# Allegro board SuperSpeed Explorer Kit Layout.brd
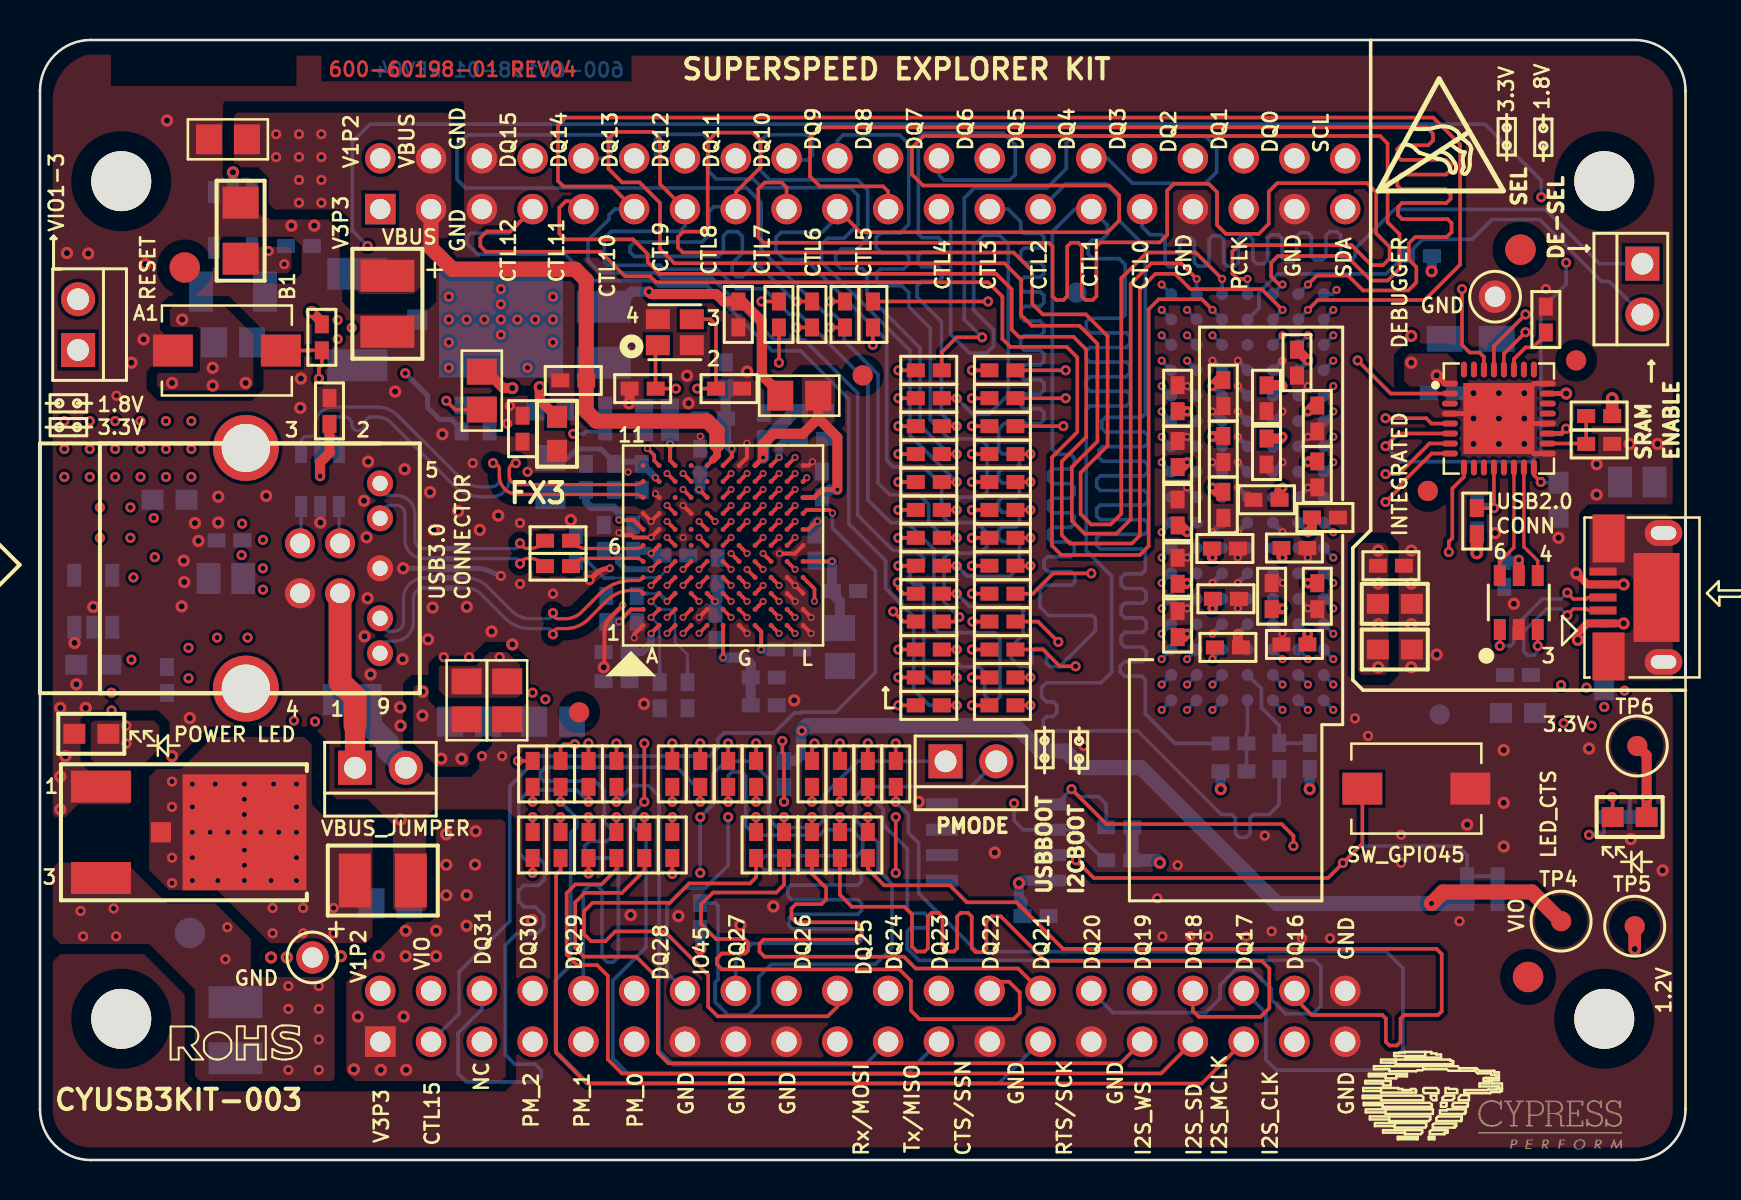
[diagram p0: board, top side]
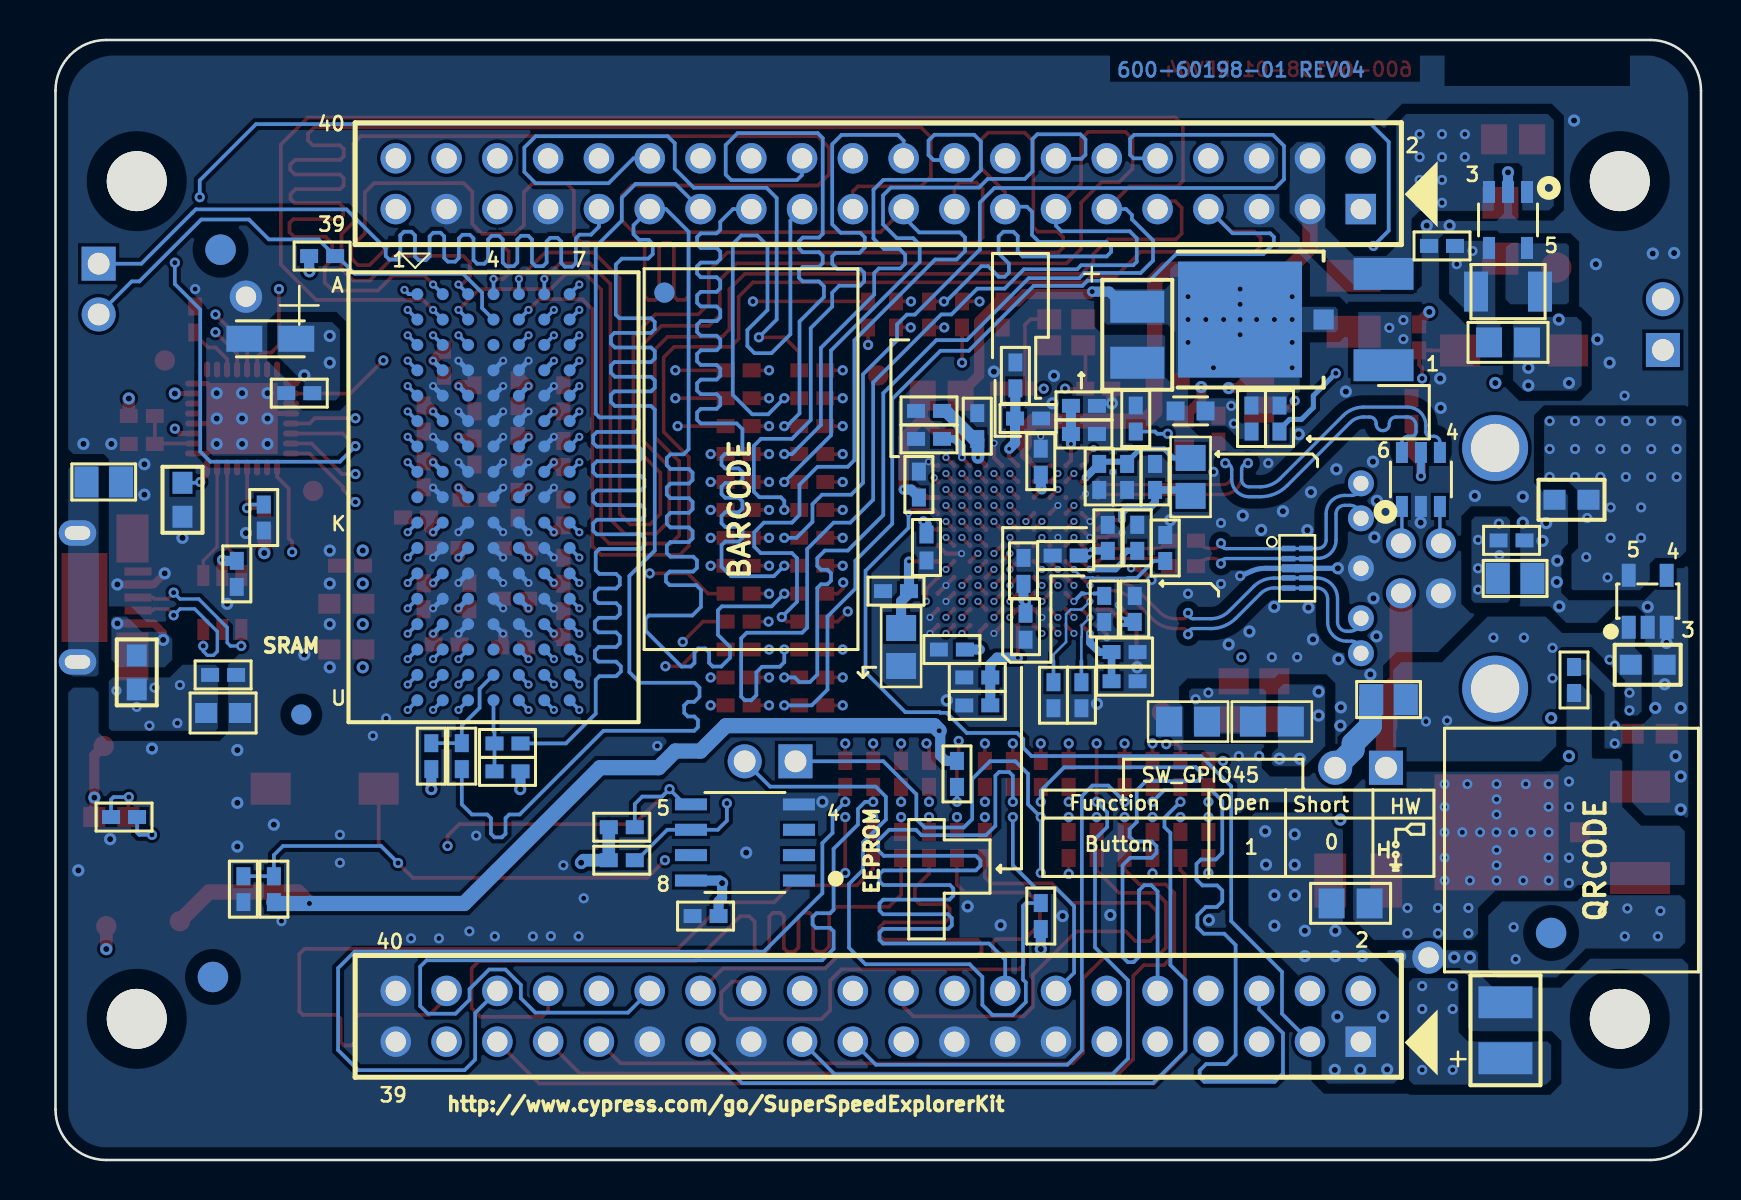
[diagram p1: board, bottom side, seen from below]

Outline 82.3 x 56.04 mm; copper layers: TOP, L02_GND1, L03_SIG1, L04_PWR1, L05_PWR2, L06_SIG2, L07_GND2, BOTTOM. Coordinates in mm from the lower left corner of the outline.
Outline path: 0,53.5 0,2.54 arc(0.74,0.74) 2.54,0 79.76,0 arc(81.55,0.74) 82.3,2.54 82.3,53.5 arc(81.55,55.29) 79.76,56.04 2.54,56.04 arc(0.74,55.29) 0,53.5

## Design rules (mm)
net group CRYSTAL: nets XTALIN XTALOUT
net group CTL3: nets CTL3 N16680016
net group CTL4_SW: nets CTL4_SW N16680012
net group DIFFPAIR0: nets SS_RX_M SS_RX_P
net group DIFFPAIR2: nets SS_DM SS_DP
net group DIFFPAIR3: nets SS_TX_M SS_TX_P
net group DIFFPAIR4.1: nets D+ D-
net group DIFFPAIR5: nets N16689306 N16689332
net group DIFFPAIR6: nets N16695553 N16695561
net group GPIO57_I2S-MCLK_VIO3_SW: nets GPIO57_I2S-MCLK_VIO3_SW N16684510
net group I2S_CLK: nets I2S_CLK N16684396
net group I2S_SD: nets I2S_SD N16684392
net group I2S_WS: nets I2S_WS N16684460
net group PCLK: nets N16679940 PCLK
net group SPI-MISO_UART-TX: nets N16684546 SPI-MISO_UART-TX
net group SPI-MOSI_UART-RX: nets N16684574 SPI-MOSI_UART-RX
net group SPI-SCK_UART-RTS: nets N16684554 SPI-SCK_UART-RTS
net group CTL0: nets N16679936
net group CTL1: nets CTL1 N16679932 N16736019
net group CTL2: nets CTL2 N16679976 N16736247
net group CTL5: nets N16680040
net group CTL6: nets N16680036
net group CTL7: nets N16678748
net group CTL8: nets N16678744
net group CTL9: nets N16678772
net group CTL10: nets N16678768
net group CTL11: nets N16678828
net group CTL12: nets N16678842
net group DQ0: nets N16678980
net group DQ1: nets N16679050
net group DQ2: nets N16679094
net group DQ3: nets N16679146
net group DQ4: nets N16679214
net group DQ5: nets N16679210
net group DQ6: nets N16679206
net group DQ7: nets N16679250
net group DQ8: nets N16679750
net group DQ9: nets N16679746
net group DQ10: nets N16679742
net group DQ11: nets N16679786
net group DQ12: nets N16679856
net group DQ13: nets N16679852
net group DQ14: nets N16679880
net group DQ15: nets N16679876
net group DQ16: nets N16683812
net group DQ17: nets N16683802
net group DQ18: nets N16683838
net group DQ19: nets N16683870
net group DQ20: nets N16683912
net group DQ21: nets N16683942
net group DQ22: nets N16683932
net group DQ23: nets N16683968
net group DQ24: nets N16684000
net group DQ25: nets N16684042
net group DQ26: nets N16684068
net group DQ27: nets N16684104
net group DQ28: nets N16684224
net group DQ29: nets N16684254
net group DQ30: nets N16684244
net group DQ31: nets N16684280

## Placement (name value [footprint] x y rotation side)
C1  10uF_10V  [CC0805]  9.4 51.07 180 top
C2  22uF_6.3V  [CC1206]  10.03 46.5 90 top
C3  0.1uF_25V  [C0402]  14.48 37.48 90 top
C4  22 uFd 16v  [C-PCC3528]  17.14 13.98 0 top
C5  10 uFd 25v  [C-PCC3528]  17.37 42.84 270 top
C6  22UF_16V  [C0805]  23.37 23 270 top
C7  2.2uF_25V  [C0603]  25.86 36.34 270 top
C8  0.1uF_25V  [C0402]  25.91 30.98 180 top
C9  0.1uF_25V  [C0402]  25.91 29.71 180 top
C10  0.1uF_25V  [C0402]  26.67 39 180 top
C11  13pF_50V  [C0402]  30.14 38.59 180 top
C12  13pF_50V  [C0402]  34.46 38.59 180 top
C13  0.1uF_25V  [C0402]  56.9 38.11 90 top
C14  0.1uF_25V  [C0402]  56.9 35.32 90 top
C15  0.1uF_25V  [C0402]  56.9 32.4 90 top
C16  0.1uF_25V  [C0402]  56.9 29.48 90 top
C17  0.1uF_25V  [C0402]  56.9 26.81 90 top
C18  0.1uF_25V  [C0402]  59.18 38.37 270 top
C19  0.1uF_25V  [C0402]  59.18 35.57 270 top
C20  0.1uF_25V  [C0402]  59.18 32.78 270 top
C21  0.1uF_25V  [C0402]  59.26 30.6 0 top
C22  0.1uF_25V  [C0402]  59.31 28.08 0 top
C23  0.1uF_25V  [C0402]  61.34 38.11 270 top
C24  0.1uF_25V  [C0402]  61.34 35.45 270 top
C25  0.1uF_25V  [C0402]  61.34 33.03 180 top
C26  0.1uF_25V  [C0402]  61.59 28.21 90 top
C27  0.1uF_25V  [C0402]  62.74 30.62 0 top
C28  0.1uF_25V  [C0402]  62.74 25.79 180 top
C29  0.1uF_25V  [C0402]  62.86 39.89 270 top
C30  0.1uF_25V  [C0402]  63.88 37.1 270 top
C31  0.1uF_25V  [C0402]  63.88 34.3 270 top
C32  0.1uF_25V  [C0402]  63.88 28.21 270 top
C33  0.1uF_25V  [C0402]  64.26 32.14 0 top
C34  0.1uF_25V  [C0402]  67.56 29.73 0 top
C35  2.2uF_25V  [C0603]  67.76 27.83 0 top
C36  2.2uF_25V  [C0603]  67.76 25.54 0 top
C37  0.01uF_25V  [C0402]  77.98 35.83 0 top
C38  1UF_16V  [CC0603]  75.95 33.03 90 bottom
C39  0.1uF_25V  [C0402]  73.23 29.33 270 bottom
C40  0.1uF_25V  [C0402]  72.9 13.55 270 bottom
C41  4.7uF / 25V  [CAPMP3216X180N]  71.55 41.09 0 bottom
C42  0.1uF_25V  [C0402]  70.1 38.37 0 bottom
C43  0.1uF_25V  [C0402]  49.78 12.21 0 bottom
C44  0.1uF_25V  [C0402]  40.26 28.46 0 bottom
C45  22UF_16V  [C0805]  40.01 25.67 270 bottom
C46  0.01uF_25V  [C0402]  39.12 33.8 90 bottom
C47  0.1uF_25V  [C0402]  38.73 30.65 270 bottom
C48  0.1uF_25V  [C0402]  38.61 37.48 0 bottom
C49  0.01uF_25V  [C0402]  38.61 36.08 0 bottom
C50  0.1uF_25V  [C0402]  37.47 25.54 0 bottom
C51  0.1uF_25V  [C0402]  36.2 36.72 90 bottom
C52  0.01uF_25V  [C0402]  36.2 24.14 0 bottom
C53  0.1uF_25V  [C0402]  36.2 22.75 0 bottom
C54  0.1uF_25V  [C0402]  34.29 39.26 90 bottom
C55  0.1uF_25V  [C0402]  33.88 29.48 90 bottom
C56  0.01uF_25V  [C0402]  33.78 26.68 270 bottom
C57  0.1uF_25V  [C0402]  33.66 37.1 180 bottom
C58  0.01uF_25V  [C0402]  33.02 34.94 90 bottom
C59  0.01uF_25V  [C0402]  31.78 30.24 0 bottom
C60  0.01uF_25V  [C0402]  30.86 37.73 180 bottom
C61  0.1uF_25V  [C0402]  30.86 36.32 180 bottom
C62  0.1uF_25V  [C0402]  30.1 34.18 270 bottom
C63  0.01uF_25V  [C0402]  29.84 27.57 270 bottom
C64  0.1uF_25V  [C0402]  29.67 31.13 90 bottom
C65  0.01uF_25V  [C0402]  28.83 25.41 180 bottom
C66  0.1uF_25V  [C0402]  28.83 23.95 180 bottom
C67  0.01uF_25V  [C0402]  28.7 34.18 270 bottom
C68  0.1uF_25V  [C0402]  28.32 27.57 90 bottom
C69  22 uFd 16v  [C-PCC3528]  28.19 41.29 270 bottom
C70  0.1uF_25V  [C0402]  28.19 31.13 90 bottom
C71  0.1uF_25V  [C0402]  27.3 34.18 90 bottom
C72  0.1uF_25V  [C0402]  26.8 30.62 90 bottom
C73  22UF_16V  [C0805]  25.65 21.93 0 bottom
C74  1.0 uF  [CAPC1608X90N_B]  25.53 37.48 0 bottom
C75  10 uFd 25v  [C-PCC3528]  9.78 6.49 90 bottom
C76  0.1uF_25V  [C0402]  9.47 31 180 bottom
C77  1UF_16V  [CC0603]  6.48 33.03 0 bottom
C78  0.1uF_25V  [C0402]  73.91 24.27 180 bottom
C79  1UF_16V  [CC0603]  73.91 22.37 0 bottom
C80  1UF_16V  [CC0603]  2.67 24.78 180 bottom
FB1  MPZ2012S601A  [FB0805]  21.34 23 270 top
FB2  MPZ2012S601A  [FB0805]  22.1 38.49 270 top
FB3  120E  [EMIFIL_BLM18P_0603]  78.23 24.4 270 bottom
FB4  MPZ2012S601A  [FB0805]  25.53 34.18 90 bottom
FB5  MPZ2012S601A  [FB0805]  21.46 21.93 180 bottom
J1  -  [UEB1112C-2AK1-4H]  3 29.6 270 top
J2  961102-6404-AR  [TE_825433-2]  1.91 40.53 90 top
J3  961102-6404-AR  [TE_825433-2]  15.76 19.63 0 top
J4  961102-6404-AR  [TE_825433-2]  45.29 19.95 0 top
J5  961102-6404-AR  [TE_825433-2]  80.14 44.84 270 top
J6  613 040 211 21  [SSW-120-03-G-D]  17.02 50.12 0 bottom
J7  613 040 211 21  [SSW-120-03-G-D]  17.02 8.46 0 bottom
J8  -  [DX4R005J91R1500]  82.3 28.15 90 top
L1  -  [BLM21PG221SN1D]  79.88 33.92 180 bottom
L2  -  [BLM21PG221SN1D]  15.63 23.04 180 bottom
L3  2.2uH  [NLCV32T-2R2M-PFR]  9.65 43.45 0 bottom
L4  -  [BLM21PG221SN1D]  9.3 29.1 180 bottom
LED1  LED_GREEN  [LED_0603]  2.57 21.32 180 top
LED2  LED_BLUE  [LED_0603]  79.5 17.16 180 top
NOREF  -  [unnamed]  74.42 9.16 0 top
NOREF#2  -  [#2]  80.29 0.06 0 top
NOREF#3  -  [#2]  -86.87 22.94 0 top
NOREF#4  -  [#2]  0 2.54 0 top
NOREF#5  -  [unnamed]  7.24 44.66 0 top
NOREF#6  -  [unnamed]  78.23 48.97 0 top
NOREF#7  -  [#2]  2.57 0 90 top
NOREF#8  -  [#2]  14.1 77.17 0 top
NOREF#9  -  [unnamed]  78.23 7.06 0 top
NOREF#10  -  [#2]  14.1 40.34 0 top
NOREF#11  -  [unnamed]  74.04 45.54 0 top
NOREF#12  -  [unnamed]  26.96 22.4 90 top
NOREF#13  -  [unnamed]  4.06 7.06 0 top
NOREF#14  -  [#2]  14.1 77.17 0 top
NOREF#15  -  [unnamed]  69.41 33.48 90 top
NOREF#16  -  [unnamed]  41.15 39.26 90 top
NOREF#17  -  [unnamed]  76.82 40 90 top
NOREF#18  -  [#2]  2.54 0 90 top
NOREF#19  -  [unnamed]  4.06 48.97 0 top
NOREF#20  -  [#2]  0 50.5 0 top
NOREF#21  -  [unnamed]  74.42 9.16 180 bottom
NOREF#22  -  [unnamed]  51.84 43.4 0 bottom
NOREF#23  -  [unnamed]  7.5 11.36 180 bottom
NOREF#24  -  [unnamed]  74.04 45.54 180 bottom
NOREF#25  -  [unnamed]  70 22.29 270 bottom
R1  100K  [R0402]  14.1 41.16 90 top
R2  1.96K  [R0402]  24.13 36.59 90 top
R3  22 Ohm  [R0402]  24.64 19.32 270 top
R4  22 Ohm  [R0402]  24.64 15.76 270 top
R5  22 Ohm  [R0402]  26.04 19.32 270 top
R6  22 Ohm  [R0402]  26.04 15.76 270 top
R7  22 Ohm  [R0402]  27.43 19.32 270 top
R8  22 Ohm  [R0402]  27.43 15.76 270 top
R9  22 Ohm  [R0402]  28.83 19.32 270 top
R10  22 Ohm  [R0402]  28.83 15.76 270 top
R11  22 Ohm  [R0402]  30.23 15.76 270 top
R12  22 Ohm  [R0402]  31.62 19.32 270 top
R13  22 Ohm  [R0402]  31.62 15.76 270 top
R14  22 Ohm  [R0402]  33.02 19.32 270 top
R15  22 Ohm  [R0402]  34.42 19.32 270 top
R16  180 Ohm  [R0402]  34.92 42.3 90 top
R17  22 Ohm  [R0402]  35.81 19.32 270 top
R18  22 Ohm  [R0402]  35.81 15.76 270 top
R19  22 Ohm  [R0402]  36.96 42.3 90 top
R20  22 Ohm  [R0402]  37.21 15.76 270 top
R21  0 Ohm  [CC0805]  37.97 38.24 0 top
R22  22 Ohm  [R0402]  38.61 42.3 90 top
R23  22 Ohm  [R0402]  38.61 19.32 270 top
R24  22 Ohm  [R0402]  38.61 15.76 270 top
R25  22 Ohm  [R0402]  40.01 19.32 270 top
R26  22 Ohm  [R0402]  40.01 15.76 270 top
R27  22 Ohm  [R0402]  40.26 42.3 90 top
R28  22 Ohm  [R0402]  41.4 19.32 270 top
R29  22 Ohm  [R0402]  41.4 15.76 270 top
R30  22 Ohm  [R0402]  41.66 42.3 90 top
R31  22 Ohm  [R0402]  42.8 19.32 270 top
R32  22 Ohm  [R0402]  44.45 39.51 0 top
R33  22 Ohm  [R0402]  44.45 38.11 0 top
R34  22 Ohm  [R0402]  44.45 36.72 0 top
R35  22 Ohm  [R0402]  44.45 35.32 0 top
R36  22 Ohm  [R0402]  44.45 33.92 0 top
R37  22 Ohm  [R0402]  44.45 32.53 0 top
R38  22 Ohm  [R0402]  44.45 31.13 0 top
R39  22 Ohm  [R0402]  44.45 29.73 0 top
R40  22 Ohm  [R0402]  44.45 28.33 0 top
R41  22 Ohm  [R0402]  44.45 26.94 0 top
R42  22 Ohm  [R0402]  44.45 25.54 0 top
R43  22 Ohm  [R0402]  44.45 24.14 0 top
R44  22 Ohm  [R0402]  44.45 22.75 0 top
R45  22 Ohm  [R0402]  48.13 39.51 0 top
R46  22 Ohm  [R0402]  48.13 38.11 0 top
R47  22 Ohm  [R0402]  48.13 36.72 0 top
R48  22 Ohm  [R0402]  48.13 35.32 0 top
R49  22 Ohm  [R0402]  48.13 33.92 0 top
R50  22 Ohm  [R0402]  48.13 32.53 0 top
R51  22 Ohm  [R0402]  48.13 31.13 0 top
R52  22 Ohm  [R0402]  48.13 29.73 0 top
R53  22 Ohm  [R0402]  48.13 28.33 0 top
R54  22 Ohm  [R0402]  48.13 26.94 0 top
R55  22 Ohm  [R0402]  48.13 25.54 0 top
R56  22 Ohm  [R0402]  48.13 24.14 0 top
R57  22 Ohm  [R0402]  48.13 22.75 0 top
R58  2K  [R0402]  59.41 25.65 180 top
R59  10K  [R0402]  71.86 31.97 90 top
R60  10K  [R0402]  75.31 42.05 90 top
R61  10K  [R0402]  77.98 37.22 180 top
R62  332 Ohm  [R0402]  78.87 17.16 0 bottom
R63  10K  [R0402]  71.88 32.14 90 bottom
R64  100K  [R0402]  71.37 13.55 270 bottom
R66  10K  [R0402]  68.96 45.23 0 bottom
R67  10K  [R0402]  63.5 20.21 270 bottom
R68  0 Ohm  [R0402]  61.98 20.21 90 bottom
R69  0 Ohm  [R0402]  59.69 20.84 0 bottom
R70  10K  [R0402]  59.69 19.44 180 bottom
R71  2K  [R0402]  53.98 16.65 0 bottom
R72  2K  [R0402]  53.98 15 0 bottom
R73  10K  [R0402]  37.21 19.32 270 bottom
R74  10K  [R0402]  33.02 12.21 90 bottom
R75  200 Ohm / 1%  [R0402]  32.38 23.25 270 bottom
R76  10K  [R0402]  30.99 23.25 90 bottom
R77  6.04K / 1%  [R0402]  28.27 37.1 90 bottom
R78  4.7K  [R0402]  22.48 37.1 90 bottom
R79  1.6K  [R0402]  21.08 37.1 90 bottom
R80  0 Ohm  [CC0805]  17.53 12.84 0 bottom
R81  120 Ohm  [R0402]  12.95 45.73 180 bottom
R82  0 Ohm  [CC0805]  9.65 40.91 180 bottom
R83  332 Ohm  [R0402]  6.35 24.02 270 bottom
SW1  434 123 050 816  [EVQ-PE105K]  9.35 40.5 0 top
SW2  434 123 050 816  [EVQ-PE105K]  68.83 18.58 0 top
TP1  TP_BLACK  [KEYSTONE_5001]  13.63 10.13 0 top
TP2  TP_BLACK  [KEYSTONE_5001]  72.77 43.19 0 top
TP4  TP_4060  [TP100_200MASK]  76.07 11.95 180 top
TP5  TP_4060  [TP100_200MASK]  79.76 11.7 0 top
TP6  TP_4060  [TP100_200MASK]  79.88 20.71 0 top
U1  NCP1117DT33RKG  [DPAK_4PIN_REL]  3.05 16.4 270 top
U2  -  [FX3_121_BUMP]  34.16 30.75 90 top
U3  CY7C65215  [CY7C65215-32LTXI]  72.96 37.1 0 top
U4  824 001 02  [SOT95P280X145-6N]  73.96 27.89 90 top
U5  CY7C1062DV33  [CY7C1062DV33-10BGXI]  60.39 33.16 180 bottom
U6  M24M02-DRMN6TP  [SOIC127P600X175-8N_A]  47.81 15.89 0 bottom
U7  NCP1117DTARKG  [DPAK_4PIN_REL]  15.88 42.05 90 bottom
U8  ESD Protector  [UDFN10_SP3010]  20.19 29.6 270 bottom
U9  824 001 02  [SOT95P280X145-6N]  14.01 34.05 90 bottom
U10  SC189CSKTRT  [SOT95P280X145-5N]  9.65 47.03 270 bottom
U11  NCP360SNT1G  [SOT95P275X110-5N_A]  2.67 27.95 90 bottom
Y1  CRYSTAL  [OSCCC200X250X55-4N]  31.75 41.42 0 top

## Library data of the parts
C1 C2 C10 C38 C40 C72 C79 = CAPACITOR NON-POL
C3 C39 = CAP NP
C4 C5 C69 C75 = 10 uFd Tantalum 16v 3216_2
C6-C9 C13-C37 C42-C68 C70 C71 C73 C76 C78 = Cap
C11 C12 = 12 pFd 0805_1
C41 C77 C80 = CAP
C74 = 1_1.0 uFd 0603 X5R 25V 10%
FB1 FB2 FB4 FB5 L1-L4 = INDUCTOR
FB3 = FERRITE_120 OHM_2000MA_0
J1 = GSB3211311WEU_0
J2-J5 = Header_1X2: room: DCDC-BOOST
J6 J7 = CPU CONNECTOR_0
J8 = DX4R005J91R1500
LED1 LED2 = LED
R1 R61 R63 R64 R71-R77 = R
R2 = RES_0 OHM_1/10W_0402_SMD_0
R3-R15 R17-R20 R22-R57 = R: signal model: R_R0402_22_ERJ-2RKF22R0X_22
R16 R58-R60 R62 R66 R67 R70 R79 R81 R83 = RESISTOR
R21 R80 R82 = RES_0 OHM_1/10W_0402_SMD_3
R68 R69 = R: signal model: R_R0402_0_OHM_RC0402JR-070RL_0_Ohm
R78 = RESISTOR_5
SW1 SW2 = EVQ-PE105K
TP1 TP2 = TP_LOOP_RED
TP4-TP6 = T POINT A
U1 U7 = LM1117MPX-3_1.3 SOT223
U2 = FX3_121_BUMP_10
U3 = CY7C65215_4
U4 U9 = USBLC6-2_0
U5 = CY7C1062DV33
U6 = M24M02-DR
U8 = AZ1065-06Q_0
U10 = SC189CSKTRT
U11 = NCP361SNT1G_0
Y1 = CRYSTAL_1

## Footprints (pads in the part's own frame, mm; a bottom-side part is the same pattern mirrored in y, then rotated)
BLM21PG221SN1D
  rect 1.2x1.55 smd: 1(-0.865,0) 2(0.865,0)
C0402
  rect 0.9x0.7 smd: 1(-0.65,0) 2(0.65,0)
C0603
  rect 1.1x1 smd: 1(-0.85,0) 2(0.85,0)
C0805
  rect 1.3x1.5 smd: 1(-0.95,0) 2(0.95,0)
C-PCC3528
  rect 1.6x2.7 smd: 1(-1.4,0) 2(1.4,0)
CAPC1608X90N_B
  rect 0.9x0.95 smd: 1(-0.75,0) 2(0.75,0)
CAPMP3216X180N
  rect 1.8x1.3 smd: 1(-1.3,0) 2(1.3,0)
CC0603
  rect 1.1x1 smd: 1(-0.85,0) 2(0.85,0)
CC0805
  rect 1.3x1.5 smd: 1(-0.95,0) 2(0.95,0)
CC1206
  rect 1.6x1.8 smd: 1(-1.4,0) 2(1.4,0)
CY7C1062DV33-10BGXI
  round 0.6 smd: A1(-3.81,10.16) A2(-2.54,10.16) A3(-1.27,10.16) A4(0,10.16) A5(1.27,10.16) A6(2.54,10.16) A7(3.81,10.16) B1(-3.81,8.89) B2(-2.54,8.89) B3(-1.27,8.89) B4(0,8.89) B5(1.27,8.89) B6(2.54,8.89) B7(3.81,8.89) C1(-3.81,7.62) C2(-2.54,7.62) C3(-1.27,7.62) C4(0,7.62) C5(1.27,7.62) C6(2.54,7.62) C7(3.81,7.62) D1(-3.81,6.35) D2(-2.54,6.35) D3(-1.27,6.35) D4(0,6.35) D5(1.27,6.35) D6(2.54,6.35) D7(3.81,6.35) E1(-3.81,5.08) E2(-2.54,5.08) E3(-1.27,5.08) E4(0,5.08) E5(1.27,5.08) E6(2.54,5.08) E7(3.81,5.08) F1(-3.81,3.81) F2(-2.54,3.81) F3(-1.27,3.81) F4(0,3.81) F5(1.27,3.81) F6(2.54,3.81) F7(3.81,3.81) G1(-3.81,2.54) G2(-2.54,2.54) G3(-1.27,2.54) G4(0,2.54) G5(1.27,2.54) G6(2.54,2.54) G7(3.81,2.54) H1(-3.81,1.27) H2(-2.54,1.27) H3(-1.27,1.27) H4(0,1.27) H5(1.27,1.27) H6(2.54,1.27) H7(3.81,1.27) J1(-3.81,0) J2(-2.54,0) J3(-1.27,0) J4(0,0) J5(1.27,0) J6(2.54,0) J7(3.81,0) K1(-3.81,-1.27) K2(-2.54,-1.27) K3(-1.27,-1.27) K4(0,-1.27) K5(1.27,-1.27) K6(2.54,-1.27) K7(3.81,-1.27) L1(-3.81,-2.54) L2(-2.54,-2.54) L3(-1.27,-2.54) L4(0,-2.54) L5(1.27,-2.54) L6(2.54,-2.54) L7(3.81,-2.54) M1(-3.81,-3.81) M2(-2.54,-3.81) M3(-1.27,-3.81) M4(0,-3.81) M5(1.27,-3.81) M6(2.54,-3.81) M7(3.81,-3.81) N1(-3.81,-5.08) N2(-2.54,-5.08) N3(-1.27,-5.08) N4(0,-5.08) N5(1.27,-5.08) N6(2.54,-5.08) N7(3.81,-5.08) P1(-3.81,-6.35) P2(-2.54,-6.35) P3(-1.27,-6.35) P4(0,-6.35) P5(1.27,-6.35) P6(2.54,-6.35) P7(3.81,-6.35) R1(-3.81,-7.62) R2(-2.54,-7.62) R3(-1.27,-7.62) R4(0,-7.62) R5(1.27,-7.62) R6(2.54,-7.62) R7(3.81,-7.62) T1(-3.81,-8.89) T2(-2.54,-8.89) T3(-1.27,-8.89) T4(0,-8.89) T5(1.27,-8.89) T6(2.54,-8.89) T7(3.81,-8.89) U1(-3.81,-10.16) U2(-2.54,-10.16) U3(-1.27,-10.16) U4(0,-10.16) U5(1.27,-10.16) U6(2.54,-10.16) U7(3.81,-10.16)
CY7C65215-32LTXI
  oval 0.8x0.3 smd: 1(-2.45,1.75) 2(-2.45,1.25) 3(-2.45,0.75) 4(-2.45,0.25) 5(-2.45,-0.25) 6(-2.45,-0.75) 7(-2.45,-1.25) 8(-2.45,-1.75) 17(2.45,-1.75) 18(2.45,-1.25) 19(2.45,-0.75) 20(2.45,-0.25) 21(2.45,0.25) 22(2.45,0.75) 23(2.45,1.25) 24(2.45,1.75)
  oval 0.3x0.8 smd: 9(-1.75,-2.45) 10(-1.25,-2.45) 11(-0.75,-2.45) 12(-0.25,-2.45) 13(0.25,-2.45) 14(0.75,-2.45) 15(1.25,-2.45) 16(1.75,-2.45) 25(1.75,2.45) 26(1.25,2.45) 27(0.75,2.45) 28(0.25,2.45) 29(-0.25,2.45) 30(-0.75,2.45) 31(-1.25,2.45) 32(-1.75,2.45)
  rect 3.556x3.556 smd: 33(0,0)
DPAK_4PIN_REL
  rect 1.6x3 smd: 1(-2.286,0) 3(2.286,0)
  rect 1.011x1.011 smd: 2(0,3)
  rect 5.8x6.2 smd: 4(0,7.181)
DX4R005J91R1500
  rect 0.4x1.35 smd: 1(-1.3,4.125) 2(-0.65,4.125) 3(0,4.125) 4(0.65,4.125) 5(1.3,4.125)
  rect 2.4x1.6 smd: 6(2.95,3.85) 10(-2.95,3.85)
  oval 1.276x1.876 hole 0.676x1.276: 7(3.225,1.1) 9(-3.225,1.1)
  rect 4.45x2.3 smd: 8(0,1.45)
EMIFIL_BLM18P_0603
  rect 1.1x1 smd: 1(-0.85,0) 2(0.85,0)
EVQ-PE105K
  rect 2x1.6 smd: A1(-2.7,0) B1(2.7,0)
FB0805
  rect 1.3x1.5 smd: 1(-0.95,0) 2(0.95,0)
FX3_121_BUMP
  round 0.25 smd: A1(-3.999,3.999) A2(-3.199,3.999) A3(-2.4,3.999) A4(-1.6,3.999) A5(-0.8,3.999) A6(0,3.999) A7(0.8,3.999) A8(1.6,3.999) A9(2.4,3.999) A10(3.199,3.999) A11(3.999,3.999) B1(-3.999,3.199) B2(-3.199,3.199) B3(-2.4,3.199) B4(-1.6,3.199) B5(-0.8,3.199) B6(0,3.199) B7(0.8,3.199) B8(1.6,3.199) B9(2.4,3.199) B10(3.199,3.199) B11(3.999,3.199) C1(-3.999,2.4) C2(-3.199,2.4) C3(-2.4,2.4) C4(-1.6,2.4) C5(-0.8,2.4) C6(0,2.4) C7(0.8,2.4) C8(1.6,2.4) C9(2.4,2.4) C10(3.199,2.4) C11(3.999,2.4) D1(-3.999,1.6) D2(-3.199,1.6) D3(-2.4,1.6) D4(-1.6,1.6) D5(-0.8,1.6) D6(0,1.6) D7(0.8,1.6) D8(1.6,1.6) D9(2.4,1.6) D10(3.199,1.6) D11(3.999,1.6) E1(-3.999,0.8) E2(-3.199,0.8) E3(-2.4,0.8) E4(-1.6,0.8) E5(-0.8,0.8) E6(0,0.8) E7(0.8,0.8) E8(1.6,0.8) E9(2.4,0.8) E10(3.199,0.8) E11(3.999,0.8) F1(-3.999,0) F2(-3.199,0) F3(-2.4,0) F4(-1.6,0) F5(-0.8,0) F6(0,0) F7(0.8,0) F8(1.6,0) F9(2.4,0) F10(3.199,0) F11(3.999,0) G1(-3.999,-0.8) G2(-3.199,-0.8) G3(-2.4,-0.8) G4(-1.6,-0.8) G5(-0.8,-0.8) G6(0,-0.8) G7(0.8,-0.8) G8(1.6,-0.8) G9(2.4,-0.8) G10(3.199,-0.8) G11(3.999,-0.8) H1(-3.999,-1.6) H2(-3.199,-1.6) H3(-2.4,-1.6) H4(-1.6,-1.6) H5(-0.8,-1.6) H6(0,-1.6) H7(0.8,-1.6) H8(1.6,-1.6) H9(2.4,-1.6) H10(3.199,-1.6) H11(3.999,-1.6) J1(-3.999,-2.4) J2(-3.199,-2.4) J3(-2.4,-2.4) J4(-1.6,-2.4) J5(-0.8,-2.4) J6(0,-2.4) J7(0.8,-2.4) J8(1.6,-2.4) J9(2.4,-2.4) J10(3.199,-2.4) J11(3.999,-2.4) K1(-3.999,-3.199) K2(-3.199,-3.199) K3(-2.4,-3.199) K4(-1.6,-3.199) K5(-0.8,-3.199) K6(0,-3.199) K7(0.8,-3.199) K8(1.6,-3.199) K9(2.4,-3.199) K10(3.199,-3.199) K11(3.999,-3.199) L1(-3.999,-3.999) L2(-3.199,-3.999) L3(-2.4,-3.999) L4(-1.6,-3.999) L5(-0.8,-3.999) L6(0,-3.999) L7(0.8,-3.999) L8(1.6,-3.999) L9(2.4,-3.999) L10(3.199,-3.999) L11(3.999,-3.999)
KEYSTONE_5001
  round 1.62 hole 1.02: 1(0,0)
LED_0603
  rect 1.1x1 smd: 1(-0.85,0) 2(0.85,0)
NLCV32T-2R2M-PFR
  rect 1.2x2 smd: 1(-1.6,0) 2(1.6,0)
OSCCC200X250X55-4N
  rect 1.2x1 smd: 1(-0.85,-0.65) 2(0.85,-0.65) 3(0.85,0.65) 4(-0.85,0.65)
R0402
  rect 0.9x0.7 smd: 1(-0.65,0) 2(0.65,0)
SOIC127P600X175-8N_A
  rect 1.6x0.6 smd: 1(-2.7,1.905) 2(-2.7,0.635) 3(-2.7,-0.635) 4(-2.7,-1.905) 5(2.7,-1.905) 6(2.7,-0.635) 7(2.7,0.635) 8(2.7,1.905)
SOT95P275X110-5N_A
  rect 1.15x0.7 smd: 1(-1.3,0.95) 2(-1.3,0) 3(-1.3,-0.95) 4(1.3,-0.95) 5(1.3,0.95)
SOT95P280X145-5N
  rect 1.1x0.6 smd: 1(-1.4,0.95) 2(-1.4,0) 3(-1.4,-0.95) 4(1.4,-0.95) 5(1.4,0.95)
SOT95P280X145-6N
  rect 1.05x0.6 smd: 1(-1.35,0.95) 2(-1.35,0) 3(-1.35,-0.95) 4(1.35,-0.95) 5(1.35,0) 6(1.35,0.95)
SSW-120-03-G-D
  rect 1.524x1.524 hole 1.016: 1(0,2.54)
  round 1.524 hole 1.016: 2(0,0) 3(2.54,2.54) 4(2.54,0) 5(5.08,2.54) 6(5.08,0) 7(7.62,2.54) 8(7.62,0) 9(10.16,2.54) 10(10.16,0) 11(12.7,2.54) 12(12.7,0) 13(15.24,2.54) 14(15.24,0) 15(17.78,2.54) 16(17.78,0) 17(20.32,2.54) 18(20.32,0) 19(22.86,2.54) 20(22.86,0) 21(25.4,2.54) 22(25.4,0) 23(27.94,2.54) 24(27.94,0) 25(30.48,2.54) 26(30.48,0) 27(33.02,2.54) 28(33.02,0) 29(35.56,2.54) 30(35.56,0) 31(38.1,2.54) 32(38.1,0) 33(40.64,2.54) 34(40.64,0) 35(43.18,2.54) 36(43.18,0) 37(45.72,2.54) 38(45.72,0) 39(48.26,2.54) 40(48.26,0)
TE_825433-2
  rect 1.702x1.702 hole 1.092: 1(0,0)
  round 1.702 hole 1.092: 2(2.54,0)
TP100_200MASK
  round 1.016 smd: 1(0,0)
UDFN10_SP3010
  rect 0.279x0.686 smd: 1(-0.991,-0.432) 2(-0.483,-0.432) 4(0.483,-0.432) 5(0.991,-0.432) 6(0.991,0.432) 7(0.483,0.432) 9(-0.483,0.432) 10(-0.991,0.432)
  rect 0.406x0.902 smd: 3(0,-0.324) 8(0,0.324)
UEB1112C-2AK1-4H
  round 1.5 hole 0.991: 1(1.25,12.01) 2(-1.25,12.01) 3(-1.25,10.01) 4(1.25,10.01)
  round 1.3 hole 0.762: 5(-4.25,14.01) 6(-2.5,14.01) 7(0,14.01) 8(2.5,14.01) 9(4.25,14.01)
  round 3.3 hole 2.413: 10(-6.02,7.3) 11(6.02,7.3)
unnamed
  round 1.524 smd: (0,0)

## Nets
AVDD: C7.1 C71.1 FB4.1 U2.A7(AVDD)
GND: C1.2 C2.2 C3.2 C4.2 C5.2 C6.2 C7.2 C10.2 C11.2 C12.1 C13.2 C14.2 C15.2 C16.2 C17.2 C18.2 C19.2 C20.2 C21.2 C22.2 C23.2 C24.2 C25.2 C26.2 C27.2 C28.2 C29.2 C30.2 C31.2 C32.2 C33.2 C34.2 C35.2 C36.2 C37.2 C38.1 C39.2 C40.2 C41.2 C42.2 C43.2 C44.2 C45.2 C46.2 C47.2 C48.2 C49.2 C50.2 C51.2 C52.2 C53.2 C54.2 C55.2 C56.2 C57.2 C58.2 C59.2 C60.2 C61.2 C62.2 C63.2 C64.2 C65.2 C66.2 C67.2 C68.2 C69.2 C70.2 C71.2 C72.2 C73.2 C74.2 C75.2 C76.2 C77.2 C78.2 C79.1 C80.2 J1.4(GND1) J1.7(GND-DRAIN) J6.5 J6.6 J6.33 J6.37 J7.13 J7.15 J7.17 J7.25 J7.29 J7.39 J7.40 J8.4(GND) L1.2 L4.2 LED1.2(CATHODE) R2.1 R16.1 R58.1 R60.2 R63.1 R75.2 R76.1 R77.2 R81.1 SW1.A1 SW2.B1 TP1.1 TP2.1 U1.1(ADJ) U2.A1(U3VSSQ) U2.A8(VSS12) U2.B7(AVSS) U2.B8(VSS14) U2.B9(VSS13) U2.D8(VSS5) U2.E2(VSS3) U2.G1(VSS1) U2.G11(VSS6) U2.K3(VSS10) U2.K4(VSS8) U2.L1(VSS2) U2.L2(VSS11) U2.L3(VSS9) U2.L6(VSS4) U2.L11(VSS7) U3.4(VSSD) U3.17(VSSD2) U3.20(VSSD3) U3.24(VSSA) U3.33(E-PAD) U4.2(G) U5.D3(VSS1) U5.D4(VSS2) U5.D5(VSS3) U5.E2(VSS4) U5.E4(VSS5) U5.E6(VSS6) U5.F3(VSS7) U5.F4(VSS8) U5.F5(VSS9) U5.G2(VSS10) U5.G4(VSS11) U5.G6(VSS12) U5.H3(VSS13) U5.H4(VSS14) U5.H5(VSS15) U5.J2(VSS16) U5.J4(VSS17) U5.J6(VSS18) U5.K3(VSS19) U5.K4(VSS20) U5.K5(VSS21) U5.L2(VSS22) U5.L4(VSS23) U5.L6(VSS24) U5.M3(VSS25) U5.M4(VSS26) U5.M5(VSS27) U5.N2(VSS28) U5.N4(VSS29) U5.N6(VSS30) U5.P3(VSS31) U5.P4(VSS32) U5.P5(VSS33) U6.4(VSS) U8.3 U8.8 U9.2(G) U10.2(GND) U11.2(GND) U11.3(EN_L) Y1.2 Y1.4
V1P2: C44.1 C45.1 C47.1 C49.1 C50.1 C54.1 C57.1 C58.1 C62.1 C63.1 C67.1 FB1.2 FB4.2 FB5.2 J6.2 J7.2 R82.2 TP5.1(TP) U2.B10(VDD8) U2.C3(VDD2) U2.E9(VDD4) U2.F11(VDD5) U2.H1(VDD1) U2.J11(VDD7) U2.L5(VDD6) U2.L7(VDD3)
V3P3: C13.1 C14.1 C15.1 C16.1 C17.1 C18.1 C19.1 C20.1 C21.1 C22.1 C23.1 C24.1 C25.1 C26.1 C27.1 C28.1 C29.1 C30.1 C31.1 C32.1 C33.1 C34.1 C35.1 C36.1 C41.1 C42.1 C43.1 C60.1 C61.1 C65.1 C66.1 FB2.1 J6.1 J7.1 LED2.1(ANODE) R1.2 R59.1 R61.1 R66.2 R67.2 R70.2 R71.2 R72.2 R80.2 TP6.1(TP) U2.B1(VIO4) U2.C11(VIO5) U3.1(VDDD) U3.23(VDDD2) U5.D2(VDD1) U5.D6(VDD2) U5.E3(VDD3) U5.E5(VDD4) U5.F2(VDD5) U5.F6(VDD6) U5.G3(VDD7) U5.G5(VDD8) U5.H2(VDD9) U5.H6(VDD10) U5.J3(VDD11) U5.J5(VDD12) U5.K2(VDD13) U5.K6(VDD14) U5.L3(VDD15) U5.L5(VDD16) U5.M2(VDD17) U5.M6(VDD18) U5.N3(VDD19) U5.N5(VDD20) U5.P2(VDD21) U5.P6(VDD22) U6.8(VCC)
VBUS_IN: C3.1 C80.1 L2.2 U9.5(V) U11.1(IN)
CTL0: J5.1 J6.31 R53.2
CTL1: J6.29 R40.2 R68.1
CTL2: J6.27 R54.2 R69.1
CTL3: J6.25 R39.2
CTL4_SW: J6.23 R33.2
CTL5: J6.21 R57.2 U5.A2(A1)
CTL6: J6.19 R41.2 U5.A3(A2)
CTL7: J6.17 R50.2 U5.A4(A3)
CTL8: J6.15 R22.2 U5.A5(A4)
CTL9: J6.13 R42.2 U5.A6(A5)
CTL10: J6.11 R43.2 U5.B2(A6)
CTL11: J6.9 R56.2 U5.B3(A7)
CTL12: J6.7 R44.2 U5.B5(A8)
D+: J8.3(DP) U4.1(IO1A)
D-: J8.2(DM) U4.3(IO2A)
DQ0: J6.38 R46.2 U5.A7(IO0)
DQ1: J6.36 R45.2 U5.B7(IO1)
DQ2: J6.34 R27.2 U5.C7(IO2)
DQ3: J6.32 R47.2 U5.D7(IO3)
DQ4: J6.30 R32.2 U5.E7(IO4)
DQ5: J6.28 R30.2 U5.F7(IO5)
DQ6: J6.26 R48.2 U5.G7(IO6)
DQ7: J6.24 R34.2 U5.H7(IO7)
DQ8: J6.22 R49.2 U5.K7(IO8)
DQ9: J6.20 R37.2 U5.L7(IO9)
DQ10: J6.18 R35.2 U5.M7(IO10)
DQ11: J6.16 R51.2 U5.N7(IO11)
DQ12: J6.14 R36.2 U5.P7(IO12)
DQ13: J6.12 R52.2 U5.R7(IO13)
DQ14: J6.10 R38.2 U5.T7(IO14)
DQ15: J6.8 R19.2 U5.U7(IO15)
DQ16: J7.38 R29.2 U5.A1(IO16)
DQ17: J7.36 R31.2 U5.B1(IO17)
DQ18: J7.34 R26.2 U5.C1(IO18)
DQ19: J7.32 R25.2 U5.D1(IO19)
DQ20: J7.30 R28.2 U5.E1(IO20)
DQ21: J7.28 R24.2 U5.F1(IO21)
DQ22: J7.26 R20.2 U5.G1(IO22)
DQ23: J7.24 R23.2 U5.H1(IO23)
DQ24: J7.22 R13.2 U5.K1(IO24)
DQ25: J7.20 R18.2 U5.L1(IO25)
DQ26: J7.18 R17.2 U5.M1(IO26)
DQ27: J7.16 R15.2 U5.N1(IO27)
DQ28: J7.12 R8.2 U5.P1(IO28)
DQ29: J7.10 R14.2 U5.R1(IO29)
DQ30: J7.8 R3.2 U5.T1(IO30)
DQ31: J7.6 R7.2 U5.U1(IO31)
FSLC0: R76.2 U2.B2(FSLC0) U2.B4(FSLC1) U2.E6(FSLC2)
GPIO45: C40.1 J7.14 R64.1 SW2.A1 U2.F2(GPIO45)
GPIO57_I2S-MCLK_VIO3_SW: J7.35 R6.2
I2C_SCL_FX3: J6.40 R72.1 U2.D9(I2C-GPIO58_SCL) U3.28(SCB0_2/GPIO_3/RTS#_0) U6.6(SCL)
I2C_SDA_FX3: J6.39 R71.1 U2.D10(I2C-GPIO59_SDA) U3.29(SCB0_3/GPIO_4/CTS#_0) U6.5(SDA)
I2S_CLK: J7.37 R12.2
I2S_SD: J7.33 R10.2
I2S_WS: J7.31 R11.2
INT_N_CTL15: J7.3 U2.L8(INT_N_CTL15)
PCLK: J6.35 R55.2
PMODE_0: J4.1 J7.11 U2.G4(PMODE0)
PMODE_1: J7.9 R73.2 U2.H4(PMODE1)
PMODE_2: J7.7 U2.L4(PMODE2)
RESET_IN: C72.1 R1.1 SW1.B1 U2.C5(RESET_N)
SPI-MISO_UART-TX: J7.21 R9.2 U3.2(SCB0_0/GPIO_8/RXD_0)
SPI-MOSI_UART-RX: J7.19 R4.2 U3.30(SCB0_4/GPIO_5/TXD_0)
SPI-SCK_UART-RTS: J7.27 R5.2
SPI-SSN_UART-CTS: J7.23 R62.1 U2.C1(UART-CTS_SPI-SSN)
SS_DM: U2.A10(DM) U9.6(IO1B)
SS_DP: U2.A9(DP) U9.4(IO2B)
SS_RX_M: J1.9(STDB_SSRX+) U2.A3(SSRXM) U8.5 U8.6
SS_RX_P: J1.8(STDB_SSRX-) U2.A4(SSRXP) U8.4 U8.7
SS_TX_M: C8.2 J1.5(STDB_SSTX-) U8.1 U8.10
SS_TX_P: C9.2 J1.6(STDB_SSTX+) U8.2 U8.9
SSDM: J1.2(D-) U9.1(IO1A)
SSDP: J1.3(D+) U9.3(IO2A)
U3RX_VDDQ: C68.1 C73.1 FB5.1 U2.A2(U3RXVDDQ)
U3TX_VDDQ: C6.1 C70.1 FB1.1 U2.B5(U3TXVDDQ)
USB3_VBUS: C1.1 C5.1 C10.1 C75.1 C77.1 J6.3 J6.4 U1.3(VIN) U2.E11(VBUS) U7.3(VIN) U10.1(IN1) U10.3(EN) U11.5(OUT)
V_BUS: C39.1 C78.1 C79.2 FB3.2 U3.19(VBUS) U4.5(V)
VIO: C46.1 C48.1 C51.1 C52.1 C53.1 C55.1 C56.1 J7.4 R21.2 R64.2 R73.1 R74.1 TP4.1(TP) U2.E3(VIO3) U2.F1(VIO2) U2.H11(VIO1_2) U2.L9(VIO1_1)
XTALIN: C11.1 U2.C6(XTALIN) Y1.1
XTALOUT: C12.2 U2.C7(XTALOUT) Y1.3
N02063: C76.1 J1.10(SHIELD1) J1.11(SHIELD2) L4.1
N16673785: C59.1 C64.1 FB2.2 U2.B6(CVDDQ)
N16678744: R22.1 U2.G5(CTL8)
N16678748: R50.1 U2.H8(CTL7)
N16678768: R43.1 U2.K5(CTL10)
N16678772: R42.1 U2.H6(CTL9)
N16678828: R56.1 U2.J5(CTL11)
N16678842: R44.1 U2.H5(CTL12)
N16678980: R46.1 U2.F10(DQ0)
N16679050: R45.1 U2.F9(DQ1)
N16679094: R27.1 U2.F7(DQ2)
N16679146: R47.1 U2.G10(DQ3)
N16679206: R48.1 U2.H10(DQ6)
N16679210: R30.1 U2.F8(DQ5)
N16679214: R32.1 U2.G9(DQ4)
N16679250: R34.1 U2.H9(DQ7)
N16679742: R35.1 U2.K11(DQ10)
N16679746: R37.1 U2.J9(DQ9)
N16679750: R49.1 U2.J10(DQ8)
N16679786: R51.1 U2.L10(DQ11)
N16679852: R52.1 U2.K9(DQ13)
N16679856: R36.1 U2.K10(DQ12)
N16679876: R19.1 U2.G8(DQ15)
N16679880: R38.1 U2.J8(DQ14)
N16679932: R40.1 U2.K7(CTL1)
N16679936: R53.1 U2.K8(CTL0)
N16679940: R55.1 U2.J6(PCLK)
N16679976: R54.1 U2.J7(CTL2)
N16680012: R33.1 U2.G7(CTL4)
N16680016: R39.1 U2.H7(CTL3)
N16680036: R41.1 U2.K6(CTL6)
N16680040: R57.1 U2.G6(CTL5)
N16683802: R31.1 U2.J4(DQ17)
N16683812: R29.1 U2.K2(DQ16)
N16683838: R26.1 U2.K1(DQ18)
N16683870: R25.1 U2.J2(DQ19)
N16683912: R28.1 U2.J3(DQ20)
N16683932: R20.1 U2.H2(DQ22)
N16683942: R24.1 U2.J1(DQ21)
N16683968: R23.1 U2.H3(DQ23)
N16684000: R13.1 U2.F4(DQ24)
N16684042: R18.1 U2.G2(DQ25)
N16684068: R17.1 U2.G3(DQ26)
N16684104: R15.1 U2.F3(DQ27)
N16684224: R8.1 U2.F5(DQ28)
N16684244: R3.1 U2.E5(DQ30)
N16684254: R14.1 U2.E1(DQ29)
N16684280: R7.1 U2.E4(DQ31)
N16684392: R10.1 U2.D2(I2S-SD)
N16684396: R12.1 U2.D1(I2S-CLK)
N16684460: R11.1 U2.D3(I2S-WS)
N16684510: R6.1 U2.C4(I2S-MCLK)
N16684546: R9.1 U2.C2(UART-TX_SPI-MISO)
N16684554: R5.1 U2.D4(UART-RTS_SPI-SCK)
N16684574: R4.1 U2.D5(UART-RX_SPI-MOSI)
N16689306: C9.1 U2.A5(SSTXP)
N16689332: C8.1 U2.A6(SSTXM)
N16689459: R77.1 U2.C8(R_USB2)
N16694632: C38.2 U3.16(VCCD)
N16695427: J8.5(SHIELD1) J8.6(SHIELD2) J8.7(SHIELD3) J8.8(SHIELD4) J8.9(SHIELD5) J8.10(SHIELD6) L1.1
N16695451: FB3.1 J8.1(VBUS)
N16695553: U3.14(USBDP) U4.6(IO1B)
N16695561: U3.15(USBDM) U4.4(IO2B)
N16697030: R59.2 R63.2 U3.12(WAKEUP)
N16697037: C37.1 R61.2 U3.18(XRESN)
N16734416: R58.2 U5.B6(A9) U5.C2(BCN) U5.C3(CE2N) U5.C5(CE3N) U5.C6(BAN) U5.R2(A10) U5.R3(BDN) U5.R5(BBN) U5.R6(A11) U5.T2(A12) U5.T3(A13) U5.T5(A14) U5.T6(A15) U5.U2(A16) U5.U3(A17) U5.U5(A18) U5.U6(A19)
N16735835: J5.2 R66.1 U5.B4(CE1N)
N16736019: R67.1 R68.2 U5.T4(WEN)
N16736247: R69.2 R70.1 U5.U4(OEN)
N16824660: U2.F6(TCK) U3.8(SCB1_3/GPIO_13/CTS#_1)
N16824680: U2.E7(TDI) U3.6(SCB1_1/GPIO_11/TXD_1)
N16824700: U2.C10(TDO) U3.5(SCB1_0/GPIO_10/RXD_1)
N16824720: U2.E8(TMS) U3.7(SCB1_2/GPIO_12/RTS#_1)
N16824740: U2.B11(TRST_N) U3.9(SCB1_4/GPIO_14/DSR#_1)
N16838394: C4.1 R80.1 R83.2 U1.2(VOUT) U1.4(TAB)
N16841024: L3.1 U10.5(LX)
N16841026: C2.1 L3.2 R81.2 R82.1 U10.4(VOUT)
N16887907: J4.2 R74.2
N16887965: J3.2 L2.1
N16887968: J1.1(VBUS) J3.1
N16904489: C69.1 R16.2 R21.1 R78.2 R79.2 U7.2(VOUT) U7.4(TAB)
N16904549: C74.1 J2.2 R2.2 R78.1 U7.1(ADJ)
N16904665: J2.1 R79.1
N17011056: LED2.2(CATHODE) R62.2
N17082147: R75.1 U2.B3(R_USB3)
N17153947: R60.1 U3.27(SCB0_1/GPO_2/DSR#_0)
N169156910: LED1.1(ANODE) R83.1

Pads without a net: J7 5; U2 A11 C9 D6 D7 D11 E10; U3 3 10 11 13 21 22 25 26 31 32; U5 C4 J1 J7 R4; U6 1 2 3 7; U11 4

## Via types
v1: diameter 0.356, hole 0.203, TOP to BOTTOM, 111 vias
v2: diameter 0.508, hole 0.254, TOP to BOTTOM, 310 vias
v3: diameter 0.406, hole 0.203, TOP to BOTTOM, 113 vias
v4: diameter 0.61, hole 0.305, TOP to BOTTOM, 151 vias

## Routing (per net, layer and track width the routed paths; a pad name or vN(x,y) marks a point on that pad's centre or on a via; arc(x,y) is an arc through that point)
AVDD: length 8
  TOP w0.203: v1(28.96,32.02) 29.69,32.02 U2.A7
  TOP w0.508: C7.1 25.78,37.24 24.99,38.02 v4(24.99,38.67)
  BOTTOM w0.381: v1(28.96,32.02) 28.96,32.4 28.7,32.65 27.56,32.65 27.3,32.91 C71.1 25.83,33.53 FB4.1
GND: length 54
  TOP w0.203: U2.K4 v1(37.76,28.75) U2.L3 ; U2.L2 v1(38.56,27.15) ; U2.G1 v1(35.36,26.35) ; U2.L11 38.44,34.75 v1(38.63,34.94) ; U2.G11 35.36,35.14 v1(35.36,35.87) ; U2.A1 29.72,26.3 v1(29.72,26.13) ; U2.B8 30.96,32.35 v1(30.56,31.95) 30.16,32.35 U2.A8 ; U2.B7 30.81,31.39 30.81,31.39 v1(30.56,31.15) 29.7,31.15 29.59,31.26 29.08,31.26 v1(28.96,31.38) ; U2.K3 v1(37.76,27.95) ; v1(32.96,27.15) 33.23,27.42 U2.E2 ; v1(38.56,26.35) U2.L1 ; U2.B9 v1(30.78,33.33) ; U2.L6 37.76,30.34 v1(36.98,30.34) ; U2.D8 v1(32.16,32.75) ; v1(29.14,27.77) 28.57,27.19 arc(28.32,26.82) 28.23,26.38 28.23,24.69 v4(28.19,24.65)
  TOP w0.254: v4(74.23,38.37) 74.71,38.85 U3.24 ; v4(74.23,35.83) 74.71,35.35 U3.17 ; U3.4 71.44,37.35 v4(71.69,37.1) ; U3.20 74.48,36.85 v4(74.23,37.1) ; v2(27.48,29.02) 27.76,29.3 arc(28.1,29.53) v3(28.5,29.6)
  TOP w0.381: v4(79.2,28.8) J8.4 77.39,28.8 v4(76.84,29.35)
  TOP w0.508: C11.2 29.49,37.89 v4(29.46,37.86) ; v3(59.91,26.33) 59.91,25.8 R58.1
  BOTTOM w0.254: U5.G4 v3(59.91,36.18) ; 60.39,39.51 v3(59.91,39.99) ; U5.N6 v3(57.37,27.6) ; 59.12,39.51 v3(58.64,39.99) ; U5.M5 v3(58.64,28.87) ; U5.E6 v3(57.37,38.72) ; U5.E2 v3(63.41,38.72) ; U5.F5 v3(58.64,37.45) ; U5.H4 v3(59.91,34.91) ; U5.K5 v3(58.64,31.41) ; 57.85,30.62 v3(57.37,30.14) ; U5.G2 v3(63.41,36.18) ; U5.J6 v3(57.37,33.64) ; U5.J2 v3(63.41,33.64) ; U5.M3 v3(62.14,28.87) ; U5.F4 v3(59.91,37.45) ; U5.K4 v3(59.91,31.41) ; U5.H5 v3(58.64,34.91) ; U5.P5 v3(58.64,26.33) ; U5.G6 v3(57.37,36.18) ; U5.P4 v3(59.91,26.33) ; U5.K3 v3(62.14,31.41) ; 62.93,30.62 v3(63.41,30.14) ; U5.H3 v3(62.14,34.91) ; 60.39,30.62 v3(59.91,30.14) ; U5.N2 v3(63.41,27.6) ; U8.8 v4(18.16,29.6) ; U5.N4 v3(59.91,27.6) ; U5.J4 v3(59.91,33.64) ; U5.M4 v3(59.91,28.87) ; 61.66,39.51 v3(62.14,39.99) ; U5.P3 v3(62.14,26.33) ; U5.E4 v3(59.91,38.72) ; U8.3 21.81,29.6 arc(22.16,29.57) 22.48,29.46 arc(22.76,29.34) v2(23.05,29.22) ; U5.F3 v3(62.14,37.45)
  BOTTOM w0.508: U10.2 v4(9.65,49.42)
  vias: v1(29.41,34.42) v1(32.16,31.15) v1(33.02,36.21) v2(3.82,38.24) v2(20.19,25.16) v2(21.46,25.16) v2(21.64,34.87) v2(22.1,20.21) v2(23.11,20.21) v2(24.01,31.87) v2(24.01,28.82) v2(24.38,34.43) v2(25.65,28.33) v2(52.2,20.71) v2(55.88,13.09) v2(56.13,11.19) v2(56.9,14.75) v2(57.52,11.2) v2(58.42,11.19) v2(60.33,11.19) v2(61.25,16.23) v2(61.59,11.44) v2(63.12,11.09) v2(64.52,11.09) v2(65.76,22.1) v2(66.42,21.22) v2(68.07,16.27) v2(68.07,14.87) v2(70.99,11.95) v2(75.31,43.57) v4(1.02,22.62) v4(1.02,19.19) v4(1.02,17.54) v4(1.27,20.21) v4(1.35,45.38) v4(1.73,25.87) v4(1.82,23.8) v4(2.29,22.62) v4(2.41,45.35) v4(2.67,27.67) v4(4.57,39.89) v4(5.18,41.06) v4(5.26,44.82) v4(6.35,52.01) v4(6.6,20.21) v4(7.09,27.7) v4(7.19,29.99) v4(7.21,28.92) v4(7.49,22.11) v4(7.75,31.87) v4(7.92,30.98) v4(8.92,33.19) v4(8.92,31.89) v4(11.31,33.23) v4(11.56,10.14) v4(12.34,10.14) v4(12.57,46.75) v4(13.05,39.1) v4(13.02,37.63) v4(13.72,46.75) v4(14.02,31.89) v4(15.05,10.2) v4(16.21,32.98) v4(16.23,26.2) v4(16.33,31.15) v4(16.38,28.11) v4(16.41,34.94) v4(16.54,24.3) v4(17.76,38.45) v4(18.01,22.65) v4(18.03,21.73) v4(18.03,17.03) v4(18.14,25.06) v4(18.24,34.56) v4(19.41,26.05) v4(19.51,33.41) v4(19.63,27.64) v4(19.69,31.51) v4(20.12,36.31) v4(20.91,32.46) v4(21.34,27.68) v4(22,31.53) v4(22.59,26.44) v4(22.92,32.24) v4(23.62,25.79) v4(24.61,12) v4(26.54,32.02) v4(29.54,12.26) v4(30.21,22.82) v4(31.93,12.21) v4(32.36,39.24) v4(32.44,37.86) v4(35.03,11.75) v4(35.36,39.44) v4(36.68,12.69) v4(37.72,23) v4(43.94,17.92) v4(47.75,15.38) v4(68.58,30.49) v4(68.58,28.84) v4(68.58,26.81) v4(68.58,24.65) v4(69.85,25.29) v4(71.37,16.78) v4(71.69,38.37) v4(71.69,35.83) v4(72.77,31.37) v4(72.96,38.37) v4(72.96,37.1) v4(72.96,35.83) v4(73.2,20.51) v4(73.2,17.87) v4(73.2,15.68) v4(73.71,27.83) v4(75.95,31.13) v4(77.47,20.59) v4(77.85,34.81) v4(77.85,33.29) v4(79.5,35.83) v4(79.56,16.05) v4(80.9,35.83) v4(81.15,14.49)
V1P2: length 26.3
  TOP w0.183: v1(36.96,35.15) 36.71,34.9 36.71,34.9 U2.J11
  TOP w0.203: U2.F11 34.6,35.18 v1(34.6,35.58) ; U2.E9 v1(32.96,33.55) ; U2.H1 36.07,26.44 v1(36.07,25.54) ; U2.C3 31.76,28.35 v1(31.36,27.95) ; U2.L7 38.43,31.55 38.84,31.96 v1(38.89,31.96) ; U2.L5 v1(39.61,29.95) ; U2.B10 v1(30.78,34.13)
  TOP w0.635: TP5.1 v4(79.76,10.55)
  BOTTOM w0.127: C67.1 28.7,34.93 28.68,34.95 ; 30.35,28.34 30.86,28.34
  BOTTOM w0.203: v1(31.36,27.95) 30.97,28.34 30.86,28.34 ; C63.1 29.96,28.34 30.35,28.34
  BOTTOM w0.254: 28.68,34.95 28.06,35.57 26.85,35.57 26.4,35.13 FB4.2
  BOTTOM w0.305: C67.1 28.81,34.94 29.99,34.94 C62.1
  BOTTOM w0.381: v1(36.96,35.15) 36.96,35.71 37.34,36.08 C49.1 ; v1(30.78,34.13) 30.78,34.15 C62.1
  BOTTOM w0.508: v1(39.61,29.95) C44.1 39.61,28.35 40.01,27.95 C45.1 ; C54.1 34.29,37.11 C57.1 34.3,35.88 v1(34.6,35.58) ; C58.1 33.02,33.61 v1(32.96,33.55) ; C47.1 38.73,31.8 v1(38.89,31.96) ; C50.1 v1(36.07,25.54)
  vias: v4(6.6,38.88) v4(7.11,42.05) v4(8.64,39.64) v4(8.64,38.75) v4(10.29,38.88) v4(19.13,23.43) v4(19.13,22.24) v4(20.07,20.08) v4(21.08,20.08)
V3P3: length 53.6
  TOP w0.203: U2.C11 31.51,35 v1(31.51,35.83) ; v1(30.56,26.35) 30.78,26.57 U2.B1
  TOP w0.254: U3.23 v4(76.33,38.35) ; v4(69.85,39.26) 70.26,38.85 U3.1
  TOP w0.508: v3(58.64,36.18) 58.68,36.22 C19.1 ; C13.1 57.36,37.46 v3(57.37,37.45) ; C23.1 62.1,38.76 v3(62.14,38.72) ; C22.1 58.66,27.62 v3(58.64,27.6) ; v3(63.41,34.91) 63.45,34.95 C31.1 ; C17.1 57.2,26.16 v3(57.37,26.33) ; v3(57.37,31.41) 57.03,31.75 C15.1 ; C21.1 58.61,30.17 v3(58.64,30.14) ; v3(62.14,36.18) 62.06,36.1 C24.1 ; v4(23.62,38.62) 23.16,38.62 22.34,39.44 FB2.1 ; C18.1 58.93,39.02 v3(58.64,38.72) ; v3(62.14,27.6) 62.1,27.56 C26.1 ; C14.1 57.13,34.67 v3(57.37,34.91) ; C25.1 61.99,33.49 v3(62.14,33.64) ; v3(58.64,33.64) 58.85,33.43 C20.1 ; v4(66.93,24.65) 66.94,24.64 ; R1.2 14.1,41.92 v4(13.59,42.43) ; v3(63.41,26.33) 63.39,26.31 C28.1 ; C33.1 63.61,31.61 v3(63.41,31.41) ; TP6.1 80.35,20.25 v4(80.35,18.14) LED2.1 ; v3(63.41,39.99) 62.86,40.54 C29.1 ; C32.1 63.42,28.86 v3(63.41,28.87) ; v3(63.41,37.45) 63.71,37.75 C30.1 ; C27.1 62.09,30.19 v3(62.14,30.14) ; v3(57.37,28.87) 57.33,28.83 C16.1
  TOP w0.635: R61.1 v4(78.63,38.1) ; R59.1 v4(71.86,30.37)
  BOTTOM w0.254: U5.N5 v3(58.64,27.6) ; U5.F2 v3(63.41,37.45) ; 57.85,39.51 v3(57.37,39.99) ; U5.K2 v3(63.41,31.41) ; U5.E5 v3(58.64,38.72) ; 69.61,44.48 v4(69.6,44.46) ; U5.J3 v3(62.14,33.64) ; U5.E3 v3(62.14,38.72) ; U5.K6 v3(57.37,31.41) ; U5.F6 v3(57.37,37.45) ; 62.93,39.51 v3(63.41,39.99) ; 59.12,30.62 v3(58.64,30.14) ; U5.G3 v3(62.14,36.18) ; U5.N3 v3(62.14,27.6) ; U5.H6 v3(57.37,34.91) ; U5.P6 v3(57.37,26.33) ; U5.J5 v3(58.64,33.64) ; U5.G5 v3(58.64,36.18) ; U5.M6 v3(57.37,28.87) ; U5.P2 v3(63.41,26.33) ; U5.M2 v3(63.41,28.87) ; U5.H2 v3(63.41,34.91) ; 61.66,30.62 v3(62.14,30.14)
  BOTTOM w0.381: C66.1 C65.1 30.1,25.41 30.56,25.88 v1(30.56,26.35)
  BOTTOM w0.508: R70.2 59.04,18.57 v4(59.05,18.56) ; C60.1 C61.1 v1(31.51,35.83) ; U6.8 49.08,13.98 v4(48.96,13.86) 48.96,13.11 49.13,12.94 C43.1 ; R67.2 v4(63.5,18.56) ; R66.2 69.61,44.48
  BOTTOM w0.635: R71.2 R72.2 55.88,15 v4(56.01,14.87)
  vias: v4(15.7,4.54) v4(15.9,7.18) v4(16.94,10.2) v4(17.04,4.51) v4(18.19,7.18) v4(18.29,11.47) v4(18.29,10.2) v4(18.31,4.51) v4(19.81,11.47) v4(19.81,10.2) v4(20.32,16.3) v4(20.32,14.77) v4(20.32,13.25) v4(21.34,13.25) v4(21.34,11.72) v4(21.76,14.78) v4(21.79,16.45) v4(66.93,30.49) v4(66.93,28.84) v4(66.93,26.81) v4(68.58,41.23) v4(68.58,39.89)
VBUS_IN: length 4
  TOP w0.508: v2(14.01,34.22) 14.01,34.9 14.48,35.37 C3.1
  BOTTOM w0.381: U9.5 v2(14.01,34.22)
  vias: v2(3.58,23.38) v2(3.58,22.49) v2(4.57,25.03) v2(7.43,25.63) v2(7.43,24.1) v2(8.86,26.14) v2(10.38,26.14) v2(12.7,21.98) v2(13.76,21.94)
CTL0: length 91.4
  TOP w0.183: R53.2 49.66,28.33 50.67,29.35 v2(52.58,29.35)
  L03_SIG1 w0.127: v2(52.58,29.35) 52.23,29 52.23,26.72 52.4,26.55 53.07,26.55 55.12,28.6 55.12,33.4 54.92,33.59 54.59,33.59 54.39,33.38 54.39,28.7 54.15,28.46 53.82,28.46 53.58,28.7 53.58,38.13 53.2,38.5 52.39,38.5 51.39,37.5 50.95,37.5 50.6,37.85 50.6,42.1 55.12,46.62 55.12,47.58
  BOTTOM w0.183: 55.12,47.58 55.12,46.69 55.51,46.3 56.09,46.3 56.27,46.11 56.27,44.87 56.45,44.69 56.82,44.69 57,44.88 57,45.96 57.19,46.14 57.55,46.14 57.73,45.96 57.73,44.9 57.92,44.72 58.28,44.72 58.47,44.9 58.47,46.06 58.65,46.24 59.01,46.24 59.2,46.06 59.2,44.9 59.38,44.72 59.75,44.72 59.93,44.9 59.93,46.06 60.11,46.24 60.48,46.24 60.66,46.06 60.66,45.03 60.84,44.84 61.21,44.84 61.39,45.03 61.39,46.11 61.57,46.29 61.94,46.29 62.12,46.11 62.12,45.13 62.31,44.95 62.67,44.95 62.85,45.13 62.85,46.21 63.04,46.39 63.4,46.39 63.59,46.21 63.59,45.21 63.77,45.02 64.14,45.02 64.32,45.21 64.32,46.26 64.5,46.45 64.87,46.45 65.04,46.27 65.05,46.26 65.05,45.23 65.23,45.05 65.6,45.05 65.78,45.23 65.78,45.6 67.74,47.56 75.28,47.56 75.47,47.38 78,44.84 J5.1
CTL1: length 113.9
  TOP w0.183: R40.2 v2(45.85,28.33)
  BOTTOM w0.183: R68.1 61.98,17.79 61.47,17.29 60.7,17.29 60.52,17.1 60.52,16.33 60.34,16.14 59.97,16.14 59.79,16.33 59.79,17.1 59.6,17.29 59.08,17.29 54.89,21.48 50.35,21.48 50.16,21.66 50.16,22.01 50.35,22.19 50.67,22.19 50.85,22.37 50.85,22.74 50.67,22.92 50.35,22.92 50.09,23.18 50.09,23.64 50.33,23.88 53.07,23.88 53.59,24.41 53.59,29.22 52.33,30.49 52.33,37.54 52.51,37.73 54.32,37.73 54.52,37.92 54.52,38.29 54.35,38.46 52.51,38.46 52.33,38.64 52.33,39.01 52.51,39.19 54.32,39.19 54.52,39.38 54.52,39.75 54.35,39.92 52.51,39.92 52.33,40.1 52.33,40.47 52.51,40.65 54.32,40.65 54.52,40.85 54.52,41.21 54.35,41.38 52.51,41.38 52.33,41.57 52.33,41.93 52.51,42.11 54.09,42.11 54.27,42.3 54.27,44.8 53.98,45.1 52.65,45.1 52.43,45.33 52.43,45.84 52.63,46.04 53.11,46.04 53.39,46.32 53.39,46.77 52.58,47.58 51.76,47.58 50.63,46.45 50.63,35.56 50.88,35.31 51.54,35.31 51.72,35.12 51.72,34.76 51.54,34.58 50.62,34.58 50.43,34.39 50.43,34.03 50.62,33.84 51.54,33.84 51.72,33.66 51.72,33.3 51.54,33.11 50.62,33.11 50.43,32.93 50.43,32.56 50.62,32.38 51.54,32.38 51.72,32.2 51.72,31.83 51.54,31.65 50.62,31.65 50.43,31.47 50.43,31.1 50.62,30.92 51.54,30.92 51.72,30.73 51.72,30.37 51.54,30.19 50.4,30.19 50.22,30 50.22,29.63 50.4,29.44 51.58,29.44 51.77,29.26 51.77,28.94 51.58,28.76 50.25,28.76 50.01,28.53 50.01,27.67 50.44,27.24 52.63,27.24 52.78,27.09 52.78,26.48 50.99,24.69 50.52,24.69 50.34,24.87 50.34,25.41 50.16,25.59 49.79,25.59 49.61,25.41 49.61,24.87 49.42,24.69 49,24.69 48.56,25.13 48.56,25.67 49.16,26.27 49.16,27.51 48.97,27.7 46.48,27.7 v2(45.85,28.33)
CTL2: length 111.6
  TOP w0.183: R54.2 49.91,26.94 v2(50.93,25.92)
  L03_SIG1 w0.127: 50.04,47.58 50.87,47.58 52.18,46.26 52.18,45.28 49.61,42.71 49.61,36.13 50.19,35.54 50.19,33.34 51.68,31.86 51.68,25.55 51.18,25.05 51.18,21.61 50.48,20.91 50.48,17.92 50.36,17.79 49.78,17.79 49.65,17.92 49.65,21.19 50.46,22 50.46,25.46 v2(50.93,25.92)
  BOTTOM w0.183: R69.1 56.77,20.84 55.28,22.33 55.28,24.02 55.1,24.2 54.26,24.2 54.02,24.44 54.02,24.7 54.26,24.94 55.15,24.94 55.32,25.11 55.32,25.47 55.12,25.67 54.26,25.67 54.07,25.85 54.07,26.22 54.26,26.4 55.15,26.4 55.32,26.57 55.32,26.93 55.12,27.13 54.26,27.13 54.07,27.31 54.07,27.68 54.26,27.86 55.15,27.86 55.32,28.03 55.32,28.4 55.12,28.59 54.26,28.59 54.07,28.78 54.07,29.14 54.26,29.33 55.1,29.33 55.28,29.51 55.28,30.39 55.1,30.57 53.03,30.57 52.84,30.76 52.84,31.12 53.03,31.3 55.22,31.3 55.41,31.49 55.41,31.85 55.22,32.04 53.03,32.04 52.84,32.22 52.84,32.58 53.03,32.77 55.22,32.77 55.41,32.95 55.41,33.32 55.22,33.5 53.03,33.5 52.84,33.68 52.84,34.05 53.03,34.23 55.22,34.23 55.41,34.41 55.41,34.78 55.22,34.96 53.14,34.96 52.96,35.14 52.96,35.51 53.14,35.69 55.22,35.69 55.41,35.88 55.41,36.24 55.22,36.43 53.29,36.43 53.11,36.61 53.11,36.97 53.29,37.16 55.1,37.16 55.28,37.34 55.28,45.7 53.98,47 53.98,48.15 53.29,48.83 51.29,48.83 50.04,47.58
CTL3: length 43.5
  TOP w0.183: R39.2 v2(45.85,29.73)
  BOTTOM w0.183: 47.5,47.58 48.41,47.58 49.05,46.94 49.05,46.55 49.23,46.36 50.03,46.36 50.21,46.18 50.21,45.81 50.03,45.63 49.23,45.63 49.05,45.45 49.05,45.08 49.23,44.9 50.03,44.9 50.21,44.72 50.21,44.35 50.03,44.17 49.23,44.17 49.05,43.99 49.05,43.62 49.23,43.44 50.03,43.44 50.21,43.25 50.21,42.89 50.03,42.71 49.23,42.71 49.05,42.52 49.05,42.16 49.23,41.97 50.03,41.97 50.21,41.79 50.21,41.43 50.03,41.24 49.23,41.24 49.05,41.06 49.05,40.69 49.23,40.51 50.03,40.51 50.21,40.33 50.21,39.96 50.03,39.78 49.23,39.78 49.05,39.6 49.05,39.23 49.23,39.05 50.03,39.05 50.21,38.86 50.21,38.5 50.03,38.32 49.23,38.32 49.05,38.13 49.05,37.77 49.23,37.58 50.03,37.58 50.21,37.4 50.21,37.04 50.03,36.85 48.23,36.85 47.94,36.57 47.94,35.52 48.12,35.33 48.8,35.33 48.99,35.15 48.99,34.78 48.8,34.6 48.12,34.6 47.94,34.42 47.94,34.05 48.12,33.87 48.8,33.87 48.99,33.69 48.99,33.32 48.8,33.14 48.12,33.14 47.94,32.95 47.94,32.59 48.12,32.41 48.8,32.41 48.99,32.22 48.99,31.86 48.8,31.67 48.12,31.67 47.94,31.49 47.94,31.13 48.12,30.94 48.8,30.94 48.99,30.76 48.99,29.69 48.51,29.21 46.37,29.21 v2(45.85,29.73)
CTL4_SW: length 28.4
  TOP w0.183: R33.2 v2(45.85,38.11)
  BOTTOM w0.183: v2(45.85,38.11) 46.65,37.31 47.45,37.31 48.43,38.28 48.43,45.83 48,46.25 47.2,46.25 46.69,45.75 46.69,42.53 47.69,41.53 47.69,40.73 47.34,40.37 46.49,40.37 45.54,41.31 45.54,46.99 44.96,47.58
CTL5: length 110.3
  TOP w0.183: J6.21 42.42,48.46 42.17,48.71 39.01,48.71 38.51,49.21 38.51,51.17 39.01,51.66 69.35,51.66 69.66,51.35 69.66,51.01 69.43,50.77 68.07,50.77 67.88,50.59 67.88,50.22 68.07,50.04 70.32,50.04 70.56,49.8 70.56,49.54 70.32,49.31 68.07,49.31 67.88,49.12 67.88,48.76 68.07,48.57 70.28,48.57 70.54,48.31 70.54,48.09 70.34,47.88 68.12,47.88 67.91,47.68 67.91,47.28 68.12,47.08 70.4,47.08 70.59,46.88 70.59,46.42 70.35,46.18 68.78,46.18 68.46,45.86 68.46,45.05 68.83,44.68 68.83,43.9 68.44,43.51 66.17,43.51 65.42,44.25 63.86,44.25 v3(63.41,43.8) ; R57.2 v2(49.53,22.75)
  L03_SIG1 w0.127: v2(49.53,22.75) 50.06,23.28 50.06,24.63 49.2,25.49 49.2,28.36 51.2,30.36 51.2,31.77 49.81,33.16 45.65,33.16 45.32,33.5 45.32,40.94 40.89,45.37 38.21,45.37 37.81,45.77 37.81,46.27 38.58,47.04 38.58,48.12 39.17,48.7 41.29,48.7 J6.21
  BOTTOM w0.183: 62.93,43.32 v3(63.41,43.8)
CTL6: length 101
  TOP w0.183: v2(45.97,27.17) 45.96,27.17 45.73,26.94 R41.2 ; J6.19 41.04,46.42 53.39,46.42 53.97,47 53.97,48.26 53.48,48.76 44.17,48.76 43.61,49.31 43.61,50.65 44.19,51.23 67.02,51.23 67.4,50.86 67.4,46.92 67.99,46.32 67.99,44.6 67.4,44 66.57,44 65.34,45.23 61.91,45.23 61.57,44.89 61.57,44.21 61.98,43.8 v3(62.14,43.8)
  BOTTOM w0.183: v2(45.97,27.17) 45.21,27.93 45.21,30.11 45.47,30.37 47.03,30.37 47.35,30.69 47.35,31.4 46.86,31.89 45.47,31.89 45.09,32.27 45.09,33.78 44.19,34.68 42.67,34.68 42.34,35.02 42.34,41.01 38.3,45.06 37.23,45.06 36.81,45.47 36.81,46.16 37.06,46.41 39.1,46.41 39.88,47.19 J6.19 ; 61.66,43.32 v3(62.14,43.8)
CTL7: length 112.5
  TOP w0.183: 37.34,47.58 37.34,48.65 37.09,48.91 36.24,48.91 35.92,48.59 35.92,46.17 36.2,45.89 50.46,45.89 50.64,45.71 50.64,43.21 50.82,43.03 51.19,43.03 51.37,43.21 51.37,45.71 51.55,45.89 51.92,45.89 52.1,45.71 52.1,43.21 52.29,43.03 52.65,43.03 52.83,43.21 52.83,45.71 53.04,45.91 56,45.91 56.37,46.28 56.37,48.5 56.71,48.84 58.46,48.84 58.87,48.43 58.87,46.78 59.31,46.34 60.95,46.34 61.45,46.84 61.45,48.45 61.88,48.88 66.36,48.88 66.82,48.42 66.82,46.36 67.5,45.68 67.5,45.11 67.17,44.77 66.59,44.77 65.59,45.77 59.95,45.77 59.63,45.46 59.63,44.35 59.91,44.08 v3(60.39,44.08) ; R50.2 v2(49.53,32.53)
  L03_SIG1 w0.127: 37.34,47.58 37.34,48.53 37.05,48.81 36.21,48.81 35.92,48.53 35.92,46.76 35.21,46.06 35.21,45.3 35.61,44.91 40.7,44.91 44.94,40.68 44.94,29.37 45.32,28.98 46.87,28.98 47.29,29.39 47.29,32.26 47.49,32.46 48.03,32.46 48.22,32.27 48.22,31.19 48.37,31.04 48.68,31.04 49.43,31.79 49.81,31.79 50.13,31.46 50.13,30.61 50.26,30.48 50.68,30.48 50.82,30.62 50.82,31.52 49.81,32.53 v2(49.53,32.53)
  BOTTOM w0.183: 60.39,43.32 v3(60.39,44.08)
CTL8: length 89.3
  TOP w0.183: v3(59.12,44.08) 57.8,45.4 55.37,45.4 54.08,44.12 54.08,32.33 53.55,31.8 52.57,31.8 52.04,32.32 52.04,34.39 53.39,35.74 53.39,41.22 52.3,42.31 50.15,42.31 49.62,42.84 49.62,44.47 48.69,45.4 32.15,45.4 31.9,45.65 31.9,46.18 32.17,46.45 33.17,46.45 33.39,46.67 33.39,50.97 33.82,51.4 35.65,51.4 36.04,51.02 36.04,49.67 34.8,48.43 34.8,47.58 ; R22.2 v2(37.86,42.95)
  BOTTOM w0.183: 34.8,47.58 34.68,47.7 33.71,47.7 33.45,47.44 33.45,46.28 33.11,45.93 29.74,45.93 29.5,45.69 29.5,45.43 29.73,45.21 33.92,45.21 34.17,45.46 34.17,46.23 34.39,46.45 34.89,46.45 35.13,46.21 35.13,45.37 34.62,44.85 34.62,44.4 34.82,44.19 35.13,44.19 35.65,44.72 35.99,44.72 37.76,42.95 v2(37.86,42.95) ; 59.12,43.32 v3(59.12,44.08)
CTL9: length 116
  TOP w0.183: v3(57.85,44.08) 57.07,44.86 55.58,44.86 54.55,43.83 54.55,32.05 53.84,31.34 52.24,31.34 51.61,31.97 51.61,34.68 52.89,35.96 52.89,40.84 51.99,41.74 49.61,41.74 49.07,42.28 49.07,44.03 48.23,44.86 31.73,44.86 31.01,45.59 31.01,47.89 29.98,48.91 29.11,48.91 28.43,49.59 28.43,51.09 28.78,51.44 30.66,51.44 31.01,51.09 31.01,48.83 32.26,47.58 ; R42.2 v2(45.85,25.54)
  BOTTOM w0.183: v2(45.85,25.54) 45.85,24.91 46.08,24.68 46.96,24.68 47.24,24.4 47.24,23.25 47.5,23 47.82,23 48,23.18 48,26.1 47.72,26.38 44.95,26.38 44.7,26.63 44.7,30.57 43.38,31.89 42.55,31.89 41.4,33.03 41.4,38.9 38,42.3 37.49,42.3 36.2,43.6 34.83,43.6 33.86,44.57 31.2,44.57 31,44.77 28.4,44.77 28.22,44.94 28.22,46.12 28.57,46.47 31.98,46.47 32.26,46.74 32.26,47.58 ; 57.85,43.32 v3(57.85,44.08)
CTL10: length 108.3
  TOP w0.183: v3(63.41,42.53) 63.91,43.03 69.26,43.03 71.02,44.8 71.02,50.81 69.68,52.16 26.28,52.16 25.91,51.78 25.91,48.98 26.18,48.71 28.59,48.71 J6.11 ; R43.2 v2(45.85,24.14)
  BOTTOM w0.183: J6.11 28.75,47.58 28.46,47.28 28.46,47.06 27.41,46.01 27.41,45 28.02,44.38 30.84,44.38 31.1,44.12 33.62,44.12 36.72,41.02 38.24,41.02 40.89,38.37 40.89,32.27 42.67,30.49 43.81,30.49 44.2,30.11 44.2,29.72 44.01,29.54 43.69,29.54 43.51,29.35 43.51,28.99 43.69,28.8 44.01,28.8 44.2,28.62 44.2,24.29 44.57,23.92 45.1,23.92 45.32,24.14 v2(45.85,24.14) ; U5.B2 v3(63.41,42.53)
CTL11: length 112.1
  TOP w0.183: 27.18,47.58 27.18,47.66 26.87,47.97 26.29,47.97 25.97,47.65 25.97,46.35 26.27,46.06 29.66,46.06 30.39,45.33 30.39,44.94 30.99,44.34 47.83,44.34 48.6,43.56 48.6,41.55 48.96,41.19 51.69,41.19 52.32,40.55 52.32,36.18 51.1,34.95 51.1,31.26 51.51,30.84 54.6,30.84 55,31.25 55,43.55 55.79,44.34 56.77,44.34 57.53,43.57 61.1,43.57 v3(62.14,42.53) ; R56.2 v2(49.53,24.14)
  L03_SIG1 w0.127: v2(49.53,24.14) 49.17,24.14 49.03,24.01 49.03,23.28 48.79,23.04 47.9,23.04 47.6,23.34 47.6,25.55 47.08,26.07 45.48,26.07 43.79,27.76 43.79,39.53 39.81,43.52 34.9,43.52 33.8,44.61 27.56,44.61 27.18,44.99 27.18,47.58
  BOTTOM w0.183: U5.B3 v3(62.14,42.53)
CTL12: length 113.9
  TOP w0.183: 24.64,47.58 23.52,46.46 22.34,46.46 22.02,46.13 22.02,45.72 22.3,45.44 28.03,45.44 29.26,44.21 30.52,44.21 30.81,43.91 47.42,43.91 48.13,43.2 48.13,41.08 48.53,40.68 51.35,40.68 51.88,40.16 51.88,36.42 50.61,35.16 50.61,30.73 51.07,30.27 55,30.27 55.45,30.71 55.45,42.56 55.95,43.07 58.1,43.07 v3(58.64,42.53) ; R44.2 v2(45.85,22.75)
  BOTTOM w0.183: U5.B5 v3(58.64,42.53) ; 24.64,47.58 23.43,46.37 21.54,46.37 21.36,46.18 21.36,45.85 21.89,45.32 26.26,45.32 27.58,44 30.68,44 30.94,43.73 33.38,43.73 36.62,40.49 38.04,40.49 40.45,38.08 40.45,31.83 42.29,29.99 42.29,28.59 43.69,27.19 43.69,23.53 44.48,22.75 v2(45.85,22.75)
D+: length 7.7
  TOP w0.165: U4.1 v2(73.01,25.72) ; J8.3 77.42,28.15 77.34,28.07 76.68,28.07 76.39,28.36 v2(76.39,28.39)
  BOTTOM w0.165: v2(73.01,25.72) 73.54,25.72 73.71,25.88 73.71,26.65 75.13,28.07 76.07,28.07 v2(76.39,28.39)
D-: length 7.7
  TOP w0.165: U4.3 v2(74.91,25.72) ; J8.2 77.45,27.5 77.37,27.57 76.68,27.57 76.39,27.28 v2(76.39,27.25)
  BOTTOM w0.165: v2(76.39,27.25) 76.07,27.57 75.34,27.57 74.2,26.44 74.2,25.44 74.4,25.25 74.7,25.25 74.91,25.45 v2(74.91,25.72)
DQ0: length 108.8
  TOP w0.183: R46.2 v2(51.3,38.11)
  L03_SIG1 w0.127: J6.38 64.16,48.7 64.16,42.39 63.79,42.02 61.83,42.02 61.49,42.36 61.49,48.5 61.15,48.85 59.65,48.85 58.93,48.13 58.93,46.83 59.32,46.44 60.06,46.44 60.37,46.12 60.37,44.9 60.09,44.62 56.08,44.62 55.01,43.56 55.01,41.31 52.92,39.21 52.4,39.21 v2(51.3,38.11)
  L06_SIG2 w0.127: v3(56.1,43.8) 56.89,44.59 60.89,44.59 62.03,45.74 66.4,45.74 68.69,43.45 70.23,43.45 71.42,44.63 75.42,44.63 76.04,44.02 76.65,44.02 76.96,43.7 76.96,42.58 76.84,42.45 75.69,42.45 75.56,42.33 75.56,42.07 75.69,41.94 76.84,41.94 76.96,41.82 76.96,41.16 77.09,41.03 77.72,41.03 77.85,41.16 77.85,44.86 77.6,45.11 76.92,45.11 74.87,47.16 68.36,47.16 68.13,47.38 68.13,47.58 68.27,47.72 73.74,47.72 74.49,48.46 74.49,51.42 73.75,52.16 63.16,52.16 62.74,51.74 J6.38
  BOTTOM w0.183: v3(56.1,43.8) 56.58,43.32
